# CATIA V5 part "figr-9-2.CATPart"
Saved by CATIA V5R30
Part number: Part1
Bounding box of the stored display mesh (mm): x -25 to 69.61, y -139.735 to 0, z 0 to 45
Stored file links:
  D:\PROJECTS\CATIA V56R 2020\Resources\Parts File\c09_catia_v5_6r2020_prt\figr-9-2.CATPart
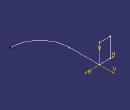
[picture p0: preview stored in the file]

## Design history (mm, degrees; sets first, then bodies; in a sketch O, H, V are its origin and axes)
Body1 (main body)
  Sketch1 on xy-plane, origin (0, 0, 0), H (1, 0, 0), V (0, 1, 0)
    line L1 (0, 0) -> (0, -70.1255)
    arc A1 centre (69.6095, -70.1255) radius 69.6095 from (0, -70.1255) to (69.6095, -139.7351) ccw
    vertical: L1 V
    tangency: A1 L1
  Sketch2 on zx-plane, origin (0, 0, 0), H (-1, 0, 0), V (0, 0, 1)
    point P1 (0, 0)
    line L1 (0, 0) -> (25, 0)
    line L2 (25, 0) -> (25, 45)
    line L3 (25, 45) -> (0, 45)
    line L4 (0, 45) -> (0, 0)
    length L3 = 25
    length L2 = 45
    coincidence: P1 H, P1 O
    horizontal: L1 H, L3 H
    vertical: L2 V, L4 V
  Rib1: profile Sketch2, centre curve Sketch1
